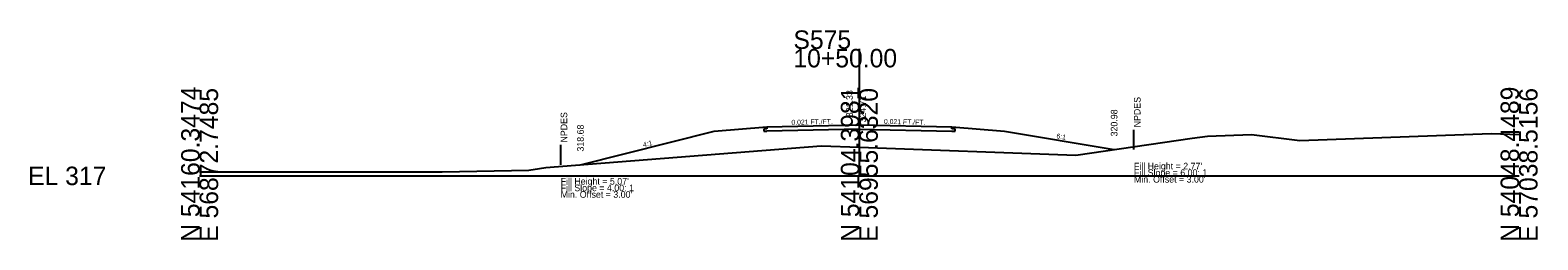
# Model space of a CAD drawing. Extents: x 10119 to 10347, y 94341 to 98867.
# Drawn here: x 10118.6 to 10347.2, y 94341.1 to 94372.9 of the extents above; entities that cross this region are included whole.
import ezdxf

# ---------------------------------------------------------------- set-up
doc = ezdxf.new("R2010")
doc.units = 0
for name, color, linetype in [('Level 10', 7, 'Continuous'), ('Level 11', 7, 'Continuous'), ('Level 12', 7, 'Continuous'), ('Level 32', 7, 'Continuous'), ('Level 33', 7, 'Continuous'), ('Level 50', 7, 'Continuous'), ('Level 55', 7, 'Continuous'), ('Level 59', 7, 'Continuous'), ('Level 6', 7, 'Continuous'), ('Level 60', 7, 'Continuous'), ('Level 63', 7, 'Continuous'), ('Level 7', 7, 'Continuous')]:
    doc.layers.add(name, color=color, linetype=linetype)

msp = doc.modelspace()

# ---------------------------------------------------------------- linework, layer by layer
at = {"layer": 'Level 11'}
for p, q in [((10230.31, 94357.94), (10229.81, 94357.93)), ((10229.81, 94357.93), (10229.81, 94357.59)), ((10229.81, 94357.59), (10230.31, 94357.6)), ((10230.31, 94358.23), (10230.31, 94357.94)), ((10258.31, 94357.94), (10258.31, 94358.23)), ((10258.81, 94357.93), (10258.31, 94357.94)), ((10258.31, 94357.6), (10258.81, 94357.59)), ((10258.81, 94357.59), (10258.81, 94357.93))]:
    msp.add_line(p, q, dxfattribs=at)
at = {"layer": 'Level 12'}
for q in [(10230.31, 94357.6), (10258.31, 94357.6)]:
    msp.add_line((10244.31, 94357.89), q, dxfattribs=at)
at = {"layer": 'Level 55'}
for p, q in [((10285.93, 94354.79), (10285.93, 94357.79)), ((10199.03, 94355.49), (10199.03, 94352.49))]:
    msp.add_line(p, q, dxfattribs=at)
at = {"layer": 'Level 59'}
for p, q in [((10230.31, 94358.23), (10244.31, 94358.52)), ((10244.31, 94358.52), (10258.31, 94358.23))]:
    msp.add_line(p, q, dxfattribs=at)
at = {"layer": 'Level 6'}
for p, q in [((10222.31, 94357.56), (10230.31, 94358.23)), ((10258.31, 94358.23), (10266.31, 94357.56))]:
    msp.add_line(p, q, dxfattribs=at)
at = {"layer": 'Level 60'}
for p, q in [((10297.07, 94356.84), (10303.74, 94357.08)), ((10303.74, 94357.08), (10311.1, 94356.15)), ((10311.1, 94356.15), (10340.06, 94357.22)), ((10340.06, 94357.22), (10344.31, 94357.07)), ((10196.77, 94352.08), (10238.51, 94355.35)), ((10238.51, 94355.35), (10244.31, 94355.14)), ((10244.31, 94355.14), (10277.13, 94353.95)), ((10277.13, 94353.95), (10294.74, 94356.51)), ((10294.74, 94356.51), (10297.07, 94356.84)), ((10144.31, 94351.44), (10181.09, 94351.44)), ((10181.09, 94351.44), (10194.23, 94351.69)), ((10194.23, 94351.69), (10195.81, 94351.91)), ((10195.81, 94351.91), (10196.77, 94352.08))]:
    msp.add_line(p, q, dxfattribs=at)
at = {"layer": 'Level 63'}
for p, q in [((10244.31, 94350.81), (10244.31, 94370.05)), ((10144.31, 94350.81), (10244.31, 94350.81)), ((10244.31, 94350.81), (10344.31, 94350.81))]:
    msp.add_line(p, q, dxfattribs=at)
at = {"layer": 'Level 7'}
for p, q in [((10202.03, 94352.49), (10222.31, 94357.56)), ((10266.31, 94357.56), (10282.93, 94354.79))]:
    msp.add_line(p, q, dxfattribs=at)

# ---------------------------------------------------------------- texts
at = {"layer": 'Level 10'}
msp.add_text('321.33', height=1, rotation=90, dxfattribs=at).set_placement((10243.31, 94359.7))
at = {"layer": 'Level 32'}
for s, rotation, p in [('0.021 FT./FT.', 1.1916, (10234.02, 94358.55)), ('0.021 FT./FT.', 358.8084, (10248.03, 94358.69)), ('6:1', 350.5377, (10274.14, 94356.51)), ('4:1', 14.0362, (10211.6, 94355.14))]:
    msp.add_text(s, height=0.75, rotation=rotation, dxfattribs=at).set_placement(p)
at = {"layer": 'Level 33'}
for s, p in [('320.98', (10283.43, 94356.79)), ('318.68', (10202.53, 94354.49))]:
    msp.add_text(s, height=1, rotation=90, dxfattribs=at).set_placement(p)
at = {"layer": 'Level 50'}
for p in [(10286.93, 94357.79), (10200.03, 94355.49)]:
    msp.add_text(' NPDES', height=1, rotation=90, dxfattribs=at).set_placement(p)
for s, p in [("Fill Height = 2.77' ", (10285.93, 94351.79)), ("Fill Height = 5.07' ", (10199.03, 94349.49)), ('Fill Slope = 6.00: 1', (10285.93, 94350.79)), ("Min. Offset = 3.00' ", (10285.93, 94349.79)), ('Fill Slope = 4.00: 1', (10199.03, 94348.49)), ("Min. Offset = 3.00' ", (10199.03, 94347.49))]:
    msp.add_text(s, height=1, dxfattribs=at).set_placement(p)
at = {"layer": 'Level 59'}
msp.add_text(' 324.71', height=1, rotation=90, dxfattribs=at).set_placement((10245.31, 94358.52))
at = {"layer": 'Level 63'}
for s, p in [('S575', (10234.32, 94370.05)), ('10+50.00', (10234.31, 94367.25)), ('EL 317', (10118.31, 94349.41))]:
    msp.add_text(s, height=2.8, dxfattribs=at).set_placement(p)
for s, p in [('N 54160.3474', (10144.31, 94340.81)), ('E 56872.7485', (10147.11, 94340.81)), ('N 54104.3981', (10244.31, 94340.81)), ('E 56955.6320', (10247.11, 94340.81)), ('N 54048.4489', (10344.31, 94340.81)), ('E 57038.5156', (10347.11, 94340.81))]:
    msp.add_text(s, height=2.8, rotation=90, dxfattribs=at).set_placement(p)

doc.saveas('drawing.dxf')
